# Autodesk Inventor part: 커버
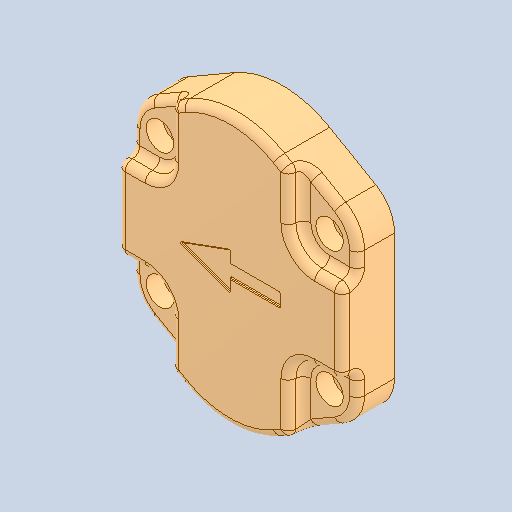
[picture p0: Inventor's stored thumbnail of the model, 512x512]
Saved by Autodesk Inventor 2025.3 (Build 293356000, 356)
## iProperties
Created: 2025-10
Part Number: 커버
Material: 알루미늄 6061
Document SubType Name: Modeling
Designer: PC-13
Density: 2.7 g/cm^3
Appearance: 기본값
Author: jhkim
Sending System: Autodesk Inventor 2026
Preprocessor: ST-DEVELOPER v20.1
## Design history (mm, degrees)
feature "솔리드2"
node "솔리드1"
